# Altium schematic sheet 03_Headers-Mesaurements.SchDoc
size A4; SheetNumber: 3; SheetTotal: 3
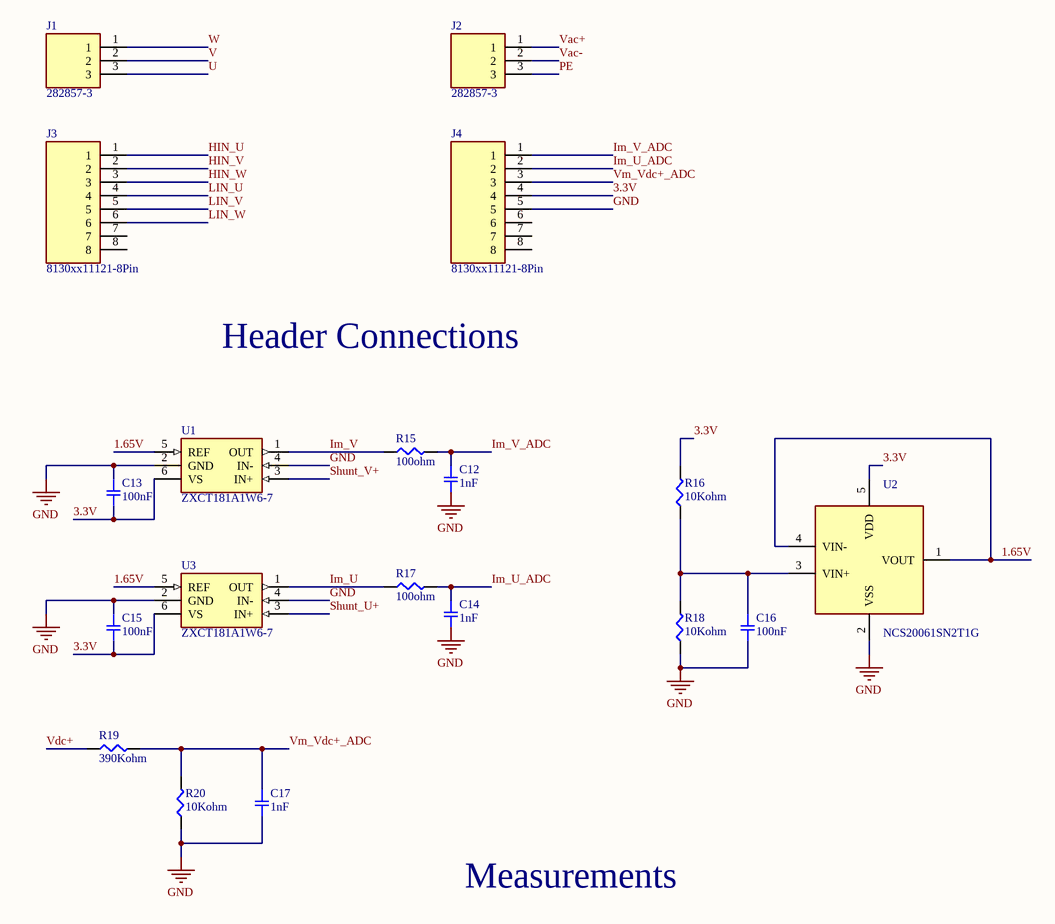
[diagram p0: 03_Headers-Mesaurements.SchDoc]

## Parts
C12  1nF  [006_SMD_0605]
C13  100nF  [006_SMD_0605]
C14  1nF  [006_SMD_0605]
C15  100nF  [006_SMD_0605]
C16  100nF  [001_SMD-1206]
C17  1nF  [006_SMD_0605]
J1  282857-3  [201_TE_282857-3]
J2  282857-3  [201_TE_282857-3]
J3  8130xx11121-8Pin  [200_HDRV6W64P0X254_1X6_1524X254X869P]
J4  8130xx11121-8Pin  [200_HDRV6W64P0X254_1X6_1524X254X869P]
R15  100ohm  [006_SMD_0605]
R16  10Kohm  [001_SMD-1206]
R17  100ohm  [006_SMD_0605]
R18  10Kohm  [001_SMD-1206]
R19  390Kohm  [001_SMD-1206]
R20  10Kohm  [001_SMD-1206]
U1  ZXCT181A1W6-7  [896_ZXCT181A1W6-7]
U2  NCS20061SN2T1G  [897_NCS20061SN2T1G]
U3  ZXCT181A1W6-7  [896_ZXCT181A1W6-7]

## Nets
GND: C12.2 C13.1 C14.2 C15.1 C16.2 C17.2 J4.5 R18.1 R20.1 U1.2(GND) U1.4(IN-) U2.2(VSS) U3.2(GND) U3.4(IN-)
1.65V: U1.5(REF) U2.1(VOUT) U2.4(VIN-) U3.5(REF)
3.3V: C13.2 C15.2 J4.4 R16.2 U1.6(VS) U2.5(VDD) U3.6(VS)
HIN_U: J3.1
HIN_V: J3.2
HIN_W: J3.3
Im_U: R17.1 U3.1(OUT)
Im_U_ADC: C14.1 J4.2 R17.2
Im_V: R15.1 U1.1(OUT)
Im_V_ADC: C12.1 J4.1 R15.2
LIN_U: J3.4
LIN_V: J3.5
LIN_W: J3.6
PE: J2.3
Shunt_U+: U3.3(IN+)
Shunt_V+: U1.3(IN+)
U: J1.3
V: J1.2
Vac+: J2.1
Vac-: J2.2
Vdc+: R19.1
Vm_Vdc+_ADC: C17.1 J4.3 R19.2 R20.2
W: J1.1
NetC16_1: C16.1 R16.1 R18.2 U2.3(VIN+)

Not connected (* = marked no-connect by the designer): J3 7 8; J4 6 7 8

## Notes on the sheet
- Header Connections
- Measurements

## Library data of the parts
C12-C15 C17 = C_0605_Template: CAP CER 0605; Part Number: GC321AD72E103KX01D; Manufacturer: Murata Electronics North America; Factory Stock: 0; Unit Price (USD): 0.3; Minimum Quantity: 1; Value: 10000pF; Tolerance: ±10%; Voltage: 250V; Temperature Coefficient: X7T
C16 = C_1206_Template: CAP CER 1206; Part Number: GC321AD72E103KX01D; Manufacturer: Murata Electronics North America; Factory Stock: 0; Unit Price (USD): 0.3; Minimum Quantity: 1; Value: 10000pF; Tolerance: ±10%; Voltage: 250V; Temperature Coefficient: X7T
J1 J2 = 282857-3: 3 Position Wire to Board Terminal Block Horizontal with Board 0.200 (5.08mm) Through Hole; MF: TE Connectivity
J3 J4 = 6130xx11121-6Pin: 2.54MM PIN HEADER; Manufacturer_Name: Wurth Elektronik; Geometry.Height: 8.69mm
R15 R17 = R_0605_Template: RES SMD 0605; Part Number: ERJ-6BQF1R0V; Manufacturer: Panasonic Electronic Components; Factory Stock: 0; Unit Price (USD): 0.05834; @ qty: 1500; Minimum Quantity: 1; Value: 1; Tolerance: ±1%; Power (Watts): 0.333W, 1/3W; Temperature Coefficient: ±200ppm/°C
R16 R18-R20 = R_1206_Template: RES SMD 1206; Part Number: ERJ-8BQF1R0V; Manufacturer: Panasonic Electronic Components; Factory Stock: 0; Unit Price (USD): 0.05778; @ qty: 1500; Minimum Quantity: 1; Value: 1; Tolerance: ±1%; Power (Watts): 0.5W, 1/2W; Temperature Coefficient: ±200ppm/°C
U1 U3 = ZXCT181A1W6-7: Bidirectional high-side current-sense amplifier, fixed gain 20 V/V, 2.7–5.5 V supply, up to 26 V common-mode input range, SOT-26 package.; MF: Texas Instruments; MP: INA181A1IDBVR
U2 = NCS20061SN2T1G: Single, rail-to-rail operational amplifier used as a voltage buffer for the 1.65 V current-sense reference.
